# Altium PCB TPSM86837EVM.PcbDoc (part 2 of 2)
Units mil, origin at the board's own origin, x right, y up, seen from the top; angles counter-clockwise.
Board outline 3000 x 2500 mil, 4 copper layers (Top Layer, Signal Layer 1, Signal Layer 2, Bottom Layer), stack 61.2 mil thick; 63 components, 16 nets, 100 pads, 288 vias.
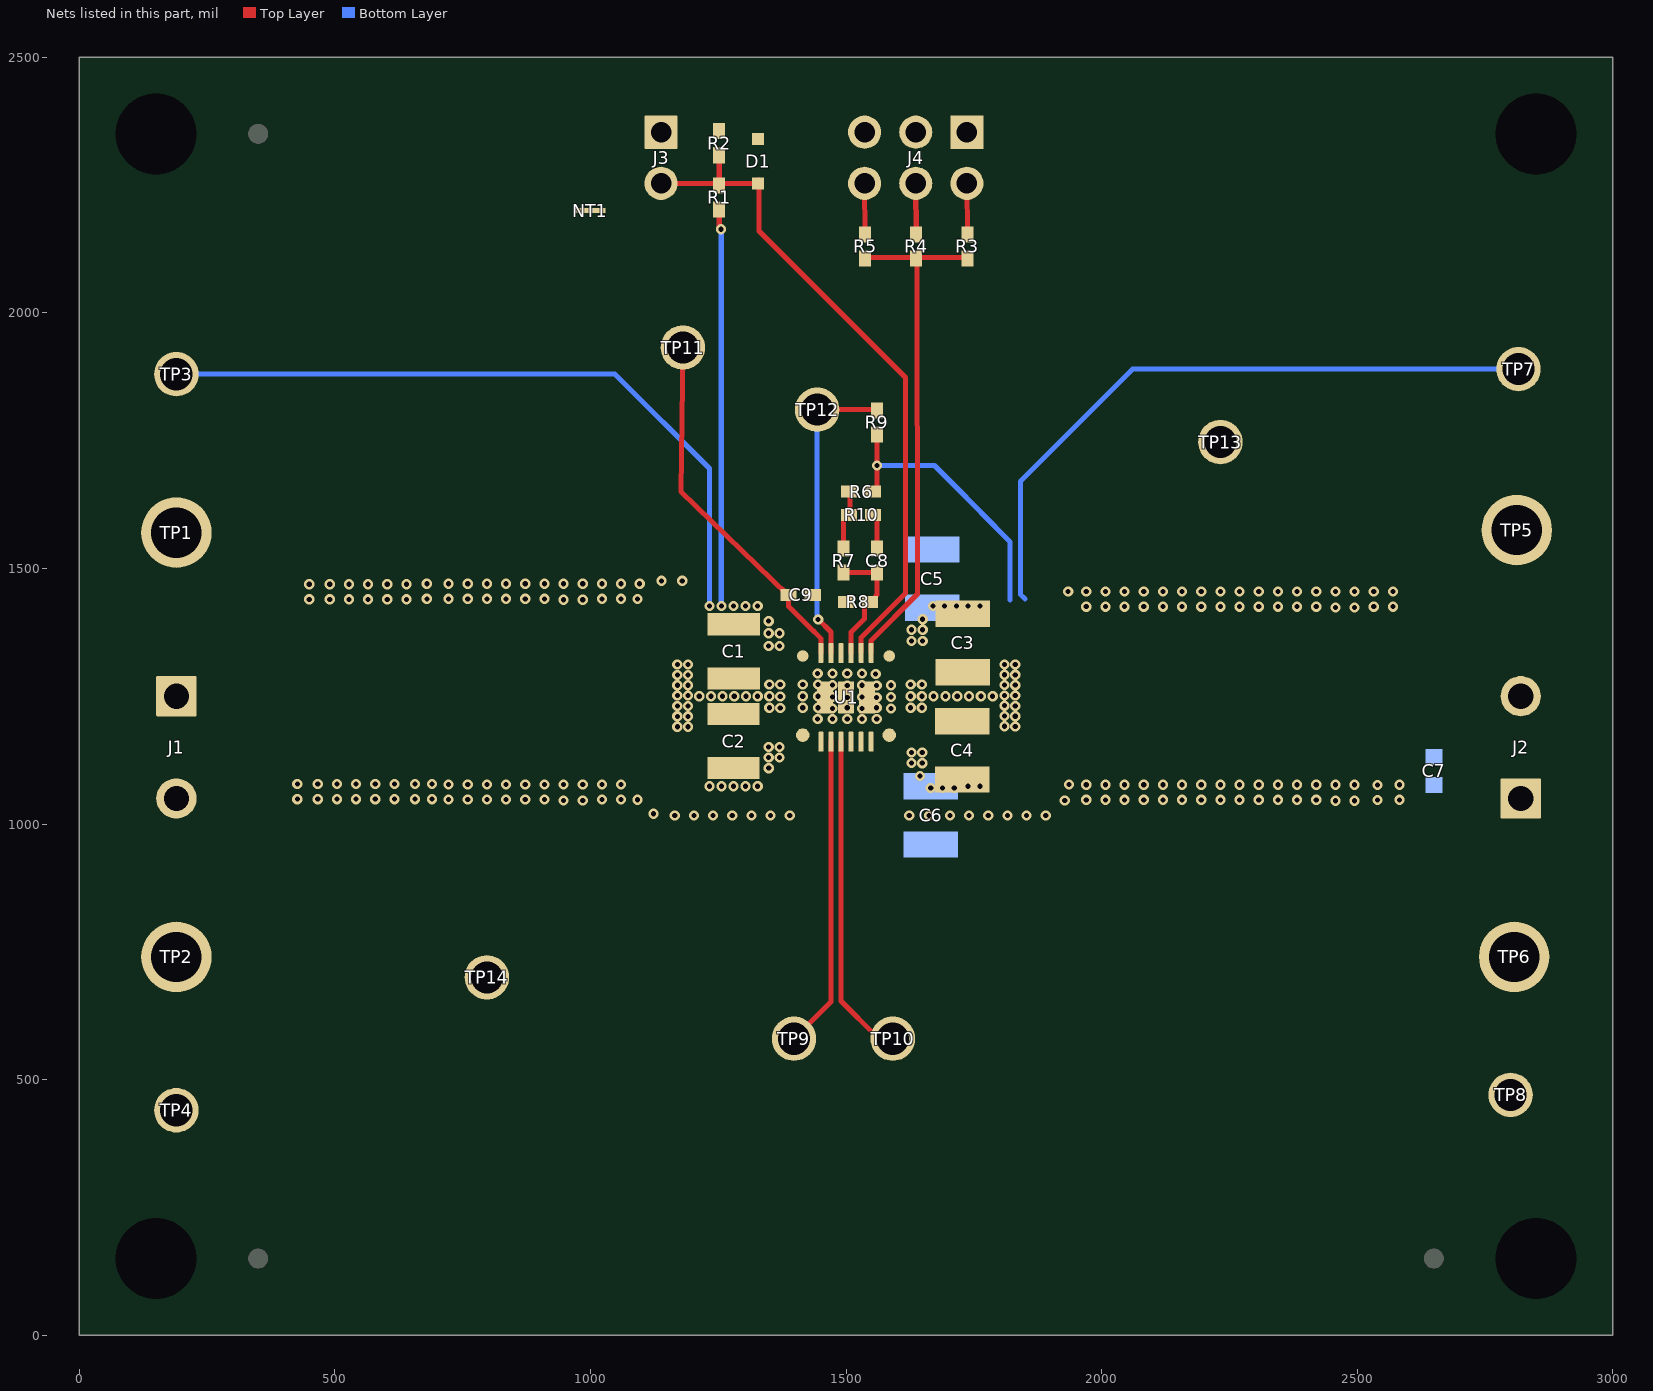
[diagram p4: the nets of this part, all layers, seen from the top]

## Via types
v1: diameter 20, hole 10, Top Layer to Bottom Layer, 288 vias

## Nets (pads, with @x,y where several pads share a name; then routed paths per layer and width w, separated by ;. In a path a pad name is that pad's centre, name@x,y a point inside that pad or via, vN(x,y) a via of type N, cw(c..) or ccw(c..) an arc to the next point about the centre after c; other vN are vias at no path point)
AGND: C9.2 D1.2 J3.1 J4.1 J4.3 J4.5 NT1.1 R2.1 R8.1 U1.5
BOOT: TP10.1 U1.12 | length 640
  Top Layer w10: U1.12@1490.16,1163.39 1490.16,690 1490.16,653.66 1560.12,583.69 TP10.1@1591.5,583.69
EN: D1.1 J3.2 R1.1 R2.2 U1.3 | length 1322
  Top Layer w10: J3.2@1138.16,2253.33 R1.1@1251.94,2253.33 ; R2.2@1251.94,2300.57 R1.1@1251.94,2253.33 ; D1.1@1328.16,2260.02 D1.1@1328.16,2253.33 R1.1@1251.94,2253.33 ; D1.1@1330,2260.02 1330,2253.33 1330,2160 1616.4,1873.6 1616.4,1451.44 1529.53,1364.56 U1.3@1529.53,1336.61
FB: C8.2 R7.1 R8.2 U1.4 | length 251.1
  Top Layer w10: R7.1@1495.19,1491.8 C8.2@1561.02,1491.8 1561.02,1448.33 1557.78,1445.09 1557.78,1441.15 1550.97,1434.34 R8.2@1547.03,1434.34 1543.1,1434.34 1536.28,1427.53 1536.28,1401.47 1509.88,1375.06 U1.4@1509.88,1334.32 ; R8.2@1540.67,1434.34 R8.2@1542.64,1434.34
MODE: R3.2 R4.2 R5.2 U1.2 | length 1007.3
  Top Layer w10: R5.2@1539.29,2108.25 R4.2@1639.06,2108.25 ; U1.2@1549.21,1336.61 1549.21,1358.97 1640.02,1449.78 R4.2@1639.06,2108.25 ; R3.2@1737.34,2108.25 R4.2@1639.06,2108.25
NetC8_1: C8.1 R10.1 | length 68.2
  Top Layer w10: R10.1@1555.12,1604.84 1561.02,1598.94 C8.1@1561.02,1539.04
NetJ4_2: J4.2 R3.1 | length 101.8
  Top Layer w10: J4.2@1736.47,2253.33 R3.1@1737.34,2151.53
NetJ4_4: J4.4 R4.1 | length 103.8
  Top Layer w10: J4.4@1636.47,2253.33 R4.1@1637.34,2149.57
NetJ4_6: J4.6 R5.1 | length 103.8
  Top Layer w10: J4.6@1536.47,2253.33 R5.1@1537.34,2149.57
NetR6_1: R6.1 R7.2 R10.2 | length 115.2
  Top Layer w10: R7.2@1495.19,1539.04 1495.19,1596.09 1503.94,1604.84 1507.87,1604.84 1507.87,1646.29 R6.1@1507.62,1646.55
PG: R9.1 TP12.1 U1.6 | length 627.7
  Top Layer w10: TP12.1@1443.64,1810.59 1559.09,1810.59 R9.1@1560.46,1809.22 R9.1@1560.46,1813.16 ; TP12.1@1444.84,1791.13 TP12.1@1447.07,1788.9 ; v1(1445.55,1400.31) 1470.51,1375.35 U1.6@1470.51,1334.32
  Bottom Layer w10: TP12.1@1439.28,1824.56 1443.64,1820.2 TP12.1@1443.64,1810.59 1443.64,1402.23 v1(1445.55,1400.31)
PGND: C1.1 C2.1 C3.2 C4.2 C5.2 C6.2 C7.2 J1.2 J2.1 NT1.2 TP2.1 TP4.1 TP6.1 TP8.1 TP13.1 TP14.1 U1.13 U1.14 U1.15 U1.17 U1.18 U1.19
  other v1: 1164.89,1016.85 1202.39,1016.85 1239.89,1016.85 1277.39,1016.85 1314.89,1016.85 1352.39,1016.85 1389.89,1016.85 1623.72,1016.85 1662.2,1016.85 1703.18,1016.85 1740.68,1016.85 1778.18,1016.85 1815.68,1016.85 1853.18,1016.85 1890.68,1016.85 1123.67,1020 2457.5,1045.53 2495,1045.53 947.5,1046.21 985,1046.21 1928.04,1046.1 1091.85,1047.45 1970,1047.23 2007.5,1047.23 2045,1047.23 2082.5,1047.23 2120,1047.23 2157.5,1047.23 2195,1047.23 2232.5,1047.23 2270,1047.23 2307.5,1047.23 2345,1047.23 2382.5,1047.23 2420,1047.23 2540,1046.79 2582.95,1047.28 426.65,1048.6 466.65,1048.6 504.15,1048.6 541.65,1048.6 579.15,1048.6 616.65,1048.6 657.07,1048.6 690,1048.6 722.5,1047.92 760,1047.92 797.5,1047.92 835,1047.92 872.5,1047.92 910,1047.92 1022.5,1047.92 1060,1047.92 2540,1076.34 722.5,1077.47 760,1077.47 797.5,1077.47 835,1077.47 872.5,1077.47 910,1077.47 947.5,1077.47 985,1077.47 1022.5,1077.47 1060,1077.47 1936.25,1077.47 1970,1076.79 2007.5,1076.79 2045,1076.79 2082.5,1076.79 2120,1076.79 2157.5,1076.79 2195,1076.79 2232.5,1076.79 2270,1076.79 2307.5,1076.79 2345,1076.79 2382.5,1076.79 2420,1076.79 2457.5,1076.79 2495,1076.79 2582.95,1076.84 426.65,1078.16 466.65,1078.16 504.15,1078.16 541.65,1078.16 579.15,1078.16 616.65,1078.16 657.07,1078.16 690,1078.16 1170,1190.33 1191,1190.33 1810,1191.23 1831,1190.66 1444.59,1205.67 1473.47,1205.67 1502.35,1205.67 1531.24,1205.67 1560.12,1205.67 1170,1210.61 1191,1210.61 1810,1211.36 1831,1210.88 1473.47,1225.87 1531.5,1225.76 1588.27,1225.76 1350,1227.32 1371.29,1226.99 1415.35,1227.32 1445,1227.32 1502.35,1227.32 1560,1227.32 1626.49,1227.32 1648.35,1227.32 1170,1230.89 1191,1230.89 1810,1231.49 1831,1231.11 1473.47,1248.54 1502.35,1247.7 1531.5,1248.44 1560,1247.7 1588.27,1248.44 1212.86,1250 1235.71,1250 1258.57,1250 1281.43,1250 1304.29,1250 1327.14,1250 1350,1250 1371.29,1249.67 1415.35,1250 1445,1250 1626.49,1250 1648.31,1250 1671.41,1250 1694.5,1250 1717.6,1250 1740.7,1250 1763.8,1250 1786.9,1250 1170,1251.16 1191,1251.16 1810,1251.62 1831,1251.33 1170,1271.44 1191,1271.44 1473.47,1271.55 1502.35,1270.71 1531.5,1271.44 1560,1270.71 1588.27,1271.44 1831,1271.55 1810,1271.74 1350,1273.01 1371.29,1272.68 1415.35,1273.01 1445,1273.01 1626.49,1273.01 1648.35,1273.01 1170,1291.72 1191,1291.72 1810,1291.87 1831,1291.78 1444.59,1294.33 1473.47,1294.33 1502.35,1294.33 1531.24,1294.33 1558.07,1293.69 1170,1312 1191,1312 1810,1312 1831,1312 2457.5,1423.41 2495,1423.41 1970,1425.11 2007.5,1425.11 2045,1425.11 2082.5,1425.11 2120,1425.11 2157.5,1425.11 2195,1425.11 2232.5,1425.11 2270,1425.11 2307.5,1425.11 2345,1425.11 2382.5,1425.11 2420,1425.11 2532.5,1425.11 2570,1425.11 450,1439.46 490,1439.46 527.5,1439.46 565,1439.46 602.5,1439.46 640,1439.46 947.5,1438.74 985,1438.74 680,1440.44 722.5,1440.44 760,1440.44 797.5,1440.44 835,1440.44 872.5,1440.44 910,1440.44 1022.5,1440.44 1060,1440.44 1091.85,1439.98 1934.65,1454.67 1970,1454.67 2007.5,1454.67 2045,1454.67 2082.5,1454.67 2120,1454.67 2157.5,1454.67 2195,1454.67 2232.5,1454.67 2270,1454.67 2307.5,1454.67 2345,1454.67 2382.5,1454.67 2420,1454.67 2457.5,1454.67 2495,1454.67 2532.5,1454.67 2570,1454.67 450,1469.02 490,1469.02 527.5,1469.02 565,1469.02 602.5,1469.02 640,1469.02 680,1470 722.5,1470 760,1470 797.5,1470 835,1470 872.5,1470 910,1470 947.5,1470 985,1470 1022.5,1470 1060,1470 1096.38,1470 1139.31,1475.72 1179.74,1475.72
SS: C9.1 TP11.1 U1.7 | length 739.7
  Top Layer w10: TP11.1@1181.01,1932.12 1177.31,1650.13 C9.1@1385.65,1448.33 ; C9.1@1376.8,1455.06 C9.1@1383.69,1448.33 ; C9.1@1376.87,1459.07 1376.87,1455.14 C9.1@1383.69,1448.33 ; U1.7@1450.83,1334.32 1450.83,1363.24 1437.03,1377.04 1436.47,1377.04 1387.62,1425.89 C9.1@1387.62,1448.33 C9.1@1383.69,1448.33
SW: TP9.1 U1.10 U1.11 | length 613.3
  Top Layer w10: TP9.1@1398.27,580 1470.47,652.2 1470.47,690.47 U1.11@1470.47,1163.39
VIN: C1.2 C2.2 J1.1 R1.2 TP1.1 TP3.1 U1.8 U1.9 | length 2165.4
  Top Layer w10: R1.2@1251.94,2202.01 1251.94,2169.75 1255.61,2166.08 v1(1255.61,2163.38)
  Bottom Layer w10: TP3.1@190,1880 1048.15,1880 1232.76,1695.39 v1(1232.76,1426.54) ; v1(1255.61,2163.38) 1256,2162.99 1256,1426.92 v1(1256.38,1426.54)
  other v1: 1232.76,1073.78 1256.38,1073.78 1280,1073.78 1303.62,1073.78 1327.24,1073.78 1348.8,1109.21 1348.76,1130 1370,1130 1348.76,1150.41 1370,1150.41 1348.76,1348.43 1370,1348.43 1348.76,1373.24 1370,1373.24 1348.76,1396.75 1280,1426.54 1303.62,1426.54 1327.24,1426.54
VOUT: C3.1 C4.1 C5.1 C6.1 C7.1 J2.2 R6.2 R9.2 TP5.1 TP7.1 U1.1 U1.16 | length 1851.8
  Top Layer w10: R6.2@1556.97,1646.55 1560.55,1650.13 v1(1560.55,1701.21) 1560.5,1701.25 R9.2@1560.46,1761.97 R9.2@1560.46,1761.97
  Bottom Layer w10: v1(1560.55,1701.21) 1673.22,1701.21 1707.44,1666.99 1820.7,1551.98 1820.7,1438.64 ; 1850,1440.44 1841,1449.45 1841,1670 2061,1890 TP7.1@2815.58,1890
  other v1: 1665.9,1070.63 1688.85,1070.63 1711.8,1070.63 1738.85,1073.78 1761.8,1073.78 1644.96,1093.94 1628.31,1119.29 1649.06,1119.06 1628.31,1140 1649.06,1139.76 1628.31,1357.95 1650,1357.95 1628.31,1379.92 1650,1379.92 1650,1400.63 1670,1426.54 1692.95,1426.54 1715.9,1426.54 1738.85,1426.54 1761.8,1426.54
pads on no net: FID1.1 FID2.1 FID3.1 FID4.1 FID5.1 FID6.1 LBL1.0 MH1.1 MH2.1 MH3.1 MH4.1 SH-JP1.0 SH-JP2.0

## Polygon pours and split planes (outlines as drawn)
VIN on Top Layer "Top Layer-VIN" (solid, remove dead copper, pour order 1012): 1429.26,1190.61 1430.12,1189.75 1430.12,1140.95 1348.76,1059.6 1210,1059.6 1210,1162.36 1373.82,1162.36 1402.36,1190.91
PGND on Top Layer "Top Layer-PGND" (solid, remove dead copper, pour order 1050): 0,2500 3000,2500 3000,0 0,0
AGND on Top Layer "Top Layer-AGND" (solid, remove dead copper, pour order 1032): 1556.1,1317.95 1444.59,1317.95 1444.59,1361.85 1000,1806.43 1000,2520 1798.31,2520 1800,2518.31 1800,1612.05 1556.1,1368.15
VIN on Top Layer "TOP_LAYER_VIN_P1004" (solid, pour order 1004): 1429.43,1309.09 1429.43,1357.72 1348.8,1438.35 1210,1438.35 1210,1337.64 1378.87,1337.64 1402.17,1309.09
VOUT on Top Layer "Top Layer-VOUT" (solid, remove dead copper, pour order 1010): 1599.41,1188.94 1625.98,1162.36 1780,1162.36 1780,1061.56 1648.6,1061.56 1569.88,1140.28 1569.88,1190.91 1597.83,1190.91
VOUT on Top Layer "Top Layer-VOUT 1" (solid, remove dead copper, pour order 1008): 1570.46,1309.67 1569.88,1310.25 1569.88,1355.15 1653.08,1438.35 1781.63,1438.35 1781.64,1337.64 1626.8,1337.64 1598.83,1309.67
VIN on Bottom Layer "Bottom Layer-VIN" (solid, remove dead copper, pour order 1022): 401.51,1392.08 401.51,1621.78 294.96,1740 40.34,1740 40.34,1109.21 1080.21,1109.21 1141.18,1050 1380,1050 1380,1162.36 1150,1162.36 1150,1188.11 1150,1337.64 1380,1337.64 1380,1389.92 1380,1450 1131.46,1450 1082.19,1391.61
PGND on Bottom Layer "Bottom Layer-PGND" (solid, remove dead copper, pour order 1052): -9.89,2506.6 3000.11,2506.6 3000.11,6.6 0.11,6.6 0.11,2496.6
VOUT on Bottom Layer "Bottom Layer-No Net" (solid, remove dead copper, pour order 1030): 3000,1180 3000,1110 1920.24,1110 1889.34,1050 1616.4,1050 1616.4,1165.45 1850,1165.45 1850,1339.77 1616.4,1340 1616.4,1450 1889.34,1450 1920.24,1390 3000,1390 3000,1190
VOUT on Bottom Layer "Bottom Layer-VOUT" (solid, remove dead copper, pour order 1044): 3000,1350 2610.26,1350 2610.26,1633.03 2717.23,1740 3000,1740
PGND on Signal Layer 1 "Signal Layer 1-PGND" (solid, remove dead copper, pour order 1034): -10,2500 3000,2500 3000,0 10,0 -10,20
PGND on Signal Layer 2 "Signal Layer 2-PGND" (solid, remove dead copper, pour order 1036): 0,2500 0,0 3000,0 3000,2500

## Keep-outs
Keep-Out Layer:
  text ".Layer_Name" at 577.16,-874.34 h30

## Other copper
Top Layer:
  rectangle net SW: 1445,1134.4 1475.85,1183.66
  text ".Layer_Name" at 577.16,-874.34 h30
Signal Layer 1:
  text ".Layer_Name" at 577.16,-874.34 h30
Signal Layer 2:
  text ".Layer_Name" at 577.16,-865.84 h30
Bottom Layer:
  text ".Layer_Name" at 577.16,-874.34 h30

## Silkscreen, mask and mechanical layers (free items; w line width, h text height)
Top Overlay:
  text "L" at 1040,2341.91 h30.79
  text "'.PRJ_Number' Rev:'.PCB_Rev'" at 2090,2238.03 h59.69
  text "EN" at 1015,2231.52 h30.71
  text "FSW  / SELECT" at 1786.47,2203.33 h35
  text "1200KHz" at 1416.66,1986.08 h24.41
  text "800KHz" at 1576.31,1986.08 h24.41
  text "500KHz" at 1718.26,1986.08 h24.41
  text "VIN" at 312.29,1539.66 h30
  text "VOUT" at 2590,1537.32 h30
  text "VIN" at 426.65,1271.44 h40
  text "VOUT" at 2457.5,1271.44 h40
  text "PGND" at 2450.13,969.61 h40
  text "PGND" at 426.65,952.56 h40
  text "PGND" at 323.34,700 h30
  text "PGND" at 2590,700 h30
  text ".Layer_Name" at 577.16,-874.34 h30
Bottom Overlay:
  text ".Layer_Name" at 577.16,-874.34 h30
Top Paste:
  text ".Layer_Name" at 577.16,-874.34 h30
Bottom Paste:
  text ".Layer_Name" at 577.16,-874.34 h30
Top Solder:
  text ".Layer_Name" at 577.16,-874.34 h30
  text ".Layer_Name" at 577.16,-874.34 h30
Bottom Solder:
  text ".Layer_Name" at 577.16,-874.34 h30
Drill Guide:
  text ".Layer_Name" at 577.16,-874.34 h30
M1 Board Outline:
  lines w47.24: 0,0 0,2500 ; 0,0 3000,0 ; 0,0 3000,0 ; 0,0 0,2500 ; 0,2500 3000,2500 ; 0,2500 3000,2500 ; 3000,0 3000,2500 ; 3000,0 3000,2500
  text ".Layer_Name" at 577.16,-874.34 h30
M2 Board Dimensions:
  rectangle: 0.16,-290.84 125.16,-165.84
  rectangle: 125.16,-415.84 500.16,-290.84
  lines w7: 0.16,-290.84 1000.16,-290.84 ; 125.16,-415.84 125.16,-165.84 ; 250.16,-415.84 250.16,-165.84 ; 500.16,-415.84 500.16,-165.84 ; 750.16,-415.84 750.16,-165.84 ; 0.16,-415.84 1000.16,-415.84 1000.16,-165.84 0.16,-165.84 0.16,-415.84
  text ".Layer_Name" at 577.16,-874.34 h30
M3 3D STEP Top:
  text ".Layer_Name" at 577.16,-874.34 h30
M4 3D STEP Bottom:
  text ".Layer_Name" at 577.16,-874.34 h30
M5 Assembly Top:
  lines w10: -291.84,-946.01 6308.16,-946.01 ; -291.84,-742.68 6310.16,-742.68 ; -291.84,-539.34 -291.84,-1149.34 3713.16,-1149.34 6310.16,-1149.34 6310.16,-539.34 -291.34,-539.34 -291.34,-1149.34 1284.16,-1149.34 ; 2173.16,-1149.34 2173.16,-539.34 ; 3440.16,-742.68 3440.16,-539.34 ; 4280.16,-742.68 4280.16,-539.34 ; 4902.16,-1155.84 4902.16,-953.01
  text "COMPONENTS MARKED 'DNP' SHOULD NOT BE POPULATED." at 1153.66,-334.34 h30
  text "ASSEMBLY VARIANT:" at 1153.16,-449.84 h30
  text ".VariantName" at 2189.16,-449.84 h30
  text "PCB VIEWED FROM TOP SIDE" at -228.34,-671.51 h30
  text "BOARD #:" at 2248.16,-671.51 h30
  text ".PRJ_Number" at 2793.66,-671.51 h30
  text "REV:" at 3638.16,-671.51 h30
  text ".PCB_Rev" at 3929.66,-671.51 h30
  text "SVN REV:" at 4476.16,-671.51 h30
  text ".VersionControl_RevNumber" at 4982.16,-671.51 h30
  text "TID #:" at 2248.16,-874.84 h30
  text ".TID" at 2793.66,-874.84 h30
  text "PLOT NAME =" at -228.34,-1080.18 h30
  text ".plot_File_Name" at 577.16,-1080.18 h30
  text "GENERATED    :" at 2250.16,-1080.18 h30
  text ".Print_Date" at 3119.66,-1080.18 h30
  text ".Print_Time" at 3848.66,-1080.18 h30
  text "TEXAS INSTRUMENTS" at 5113.16,-1080.18 h30
M6 Assembly Bottom:
  lines w10: -292.34,-743.18 6309.66,-743.18 ; -290.34,-946.51 6309.66,-946.51 ; 1115.66,-1156.34 1115.66,-953.51 ; 1737.66,-743.18 1737.66,-539.84 ; 2577.66,-743.18 2577.66,-539.84 ; 3844.66,-1149.84 3844.66,-539.84 ; 4733.66,-1149.84 6309.16,-1149.84 6309.16,-539.84 -292.34,-539.84 -292.34,-1149.84 2304.66,-1149.84 6309.66,-1149.84 6309.66,-539.84
  text "COMPONENTS MARKED 'DNP' SHOULD NOT BE POPULATED." at 6102.16,-333.84 h30
  text ".VariantName" at 5058.16,-449.84 h30
  text "ASSEMBLY VARIANT:" at 6097.16,-449.84 h30
  text ".VersionControl_RevNumber" at 1035.66,-672.01 h30
  text "SVN REV:" at 1541.66,-672.01 h30
  text ".PCB_Rev" at 2088.16,-672.01 h30
  text "REV:" at 2379.66,-672.01 h30
  text ".PRJ_Number" at 3224.16,-672.01 h30
  text "BOARD #:" at 3769.66,-672.01 h30
  text "PCB VIEWED FROM BOTTOM SIDE" at 6246.16,-672.01 h30
  text ".TID" at 3224.16,-875.34 h30
  text "TID #:" at 3769.66,-875.34 h30
  text "TEXAS INSTRUMENTS" at 904.66,-1080.68 h30
  text ".Print_Time" at 2169.16,-1080.68 h30
  text ".Print_Date" at 2898.16,-1080.68 h30
  text "GENERATED    :" at 3767.66,-1080.68 h30
  text ".plot_File_Name" at 5440.66,-1080.68 h30
  text "PLOT NAME =" at 6246.16,-1080.68 h30
M9 Title Sheet:
  drawing of 57 lines, arcs and shapes, not listed
  text "1" at 739.99,8020.66 h70
  text "2" at 3235.66,8020.66 h70
  text "3" at 5725,8020.66 h70
  text "4" at 8231.67,8020.66 h70
  text "5" at 10730.66,8020.66 h70
  text "6" at 13235.66,8020.66 h70
  text "A" at -416.34,6877.66 h70
  text "A" at 14383.66,6877.66 h70
  text "B" at -416.34,4497.66 h70
  text "B" at 14383.66,4497.66 h70
  text "C" at -416.34,2122.66 h70
  text "C" at 14383.66,2122.66 h70
  text "PROJECT TITLE:" at 11343.66,261.66 h45
  text ".PRJ_Title" at 11393.66,128.33 h70
  text "DESIGNED FOR:" at 11343.66,-39.34 h45
  text ".PRJ_Customer" at 11393.66,-179.34 h70
  text "D" at -416.34,-247.34 h70
  text "D" at 14383.66,-247.34 h70
  text "FILE NAME:" at 11343.66,-339.34 h45
  text ".PCB_File_Name_No_Path" at 11393.66,-459.34 h70
  text "Texas Instruments (TI) and/or its licensors do not warrant the accuracy or completeness of this specification" at 6374.16,-621.18 h45
  text "ENGINEER:" at 11343.66,-629.34 h45
  text "LAYOUT BY:" at 12848.66,-629.34 h45
  text "or any information contained therein. TI and/or its licensors do not warrant that this design will meet" at 6329.17,-733.85 h45
  text ".PRJ_Engineer" at 11393.66,-784.33 h70
  text ".PCB_Layout" at 12899.16,-784.33 h70
  text "the specifications, will be suitable for your application or fit for any particular purpose, or will operate in" at 6329.17,-846.51 h45
  text ".Layer_Name" at 577.16,-874.34 h30
  text "ALTIUM DESIGNER VERSION:" at 12848.66,-939.34 h45
  text "an implementation. TI and/or its licensors do not warrant that the design is production worthy. You should" at 6329.17,-959.18 h45
  text "completely validate and test your design implementation to confirm the system functionality for your application." at 6374.16,-1071.84 h45
  text ".print_Scale" at 11393.66,-1072.67 h70
  text ".Application_BuildNumber" at 12899.16,-1072.67 h70
  text "1" at 739.99,-1279.34 h70
  text "2" at 3235.66,-1279.34 h70
  text "3" at 5725,-1279.34 h70
  text "4" at 8231.67,-1279.34 h70
  text "5" at 10730.66,-1279.34 h70
  text "6" at 13235.66,-1279.34 h70
M10 Fab Notes:
  drawing of 189 lines, arcs and shapes, not listed
  text "DESIGN INFORMATION" at 12382.18,6340.33 h30
  text "MIN. TRACK WIDTH:" at 11737.62,6208.21 h30
  text "8" at 12833.86,6208.21 h30
  text "MIL" at 12988.62,6208.21 h30
  text "MIN. CLEARANCE:" at 11737.62,6084.08 h30
  text "0.2" at 12773.86,6084.08 h30
  text "mm" at 12988.62,6084.08 h30
  text "MIN. VIA PAD SIZE:" at 11737.62,5959.95 h30
  text "19" at 12803.87,5959.96 h30
  text "MIL" at 12988.62,5959.95 h30
  text "0.05mm (2MIL)" at 12432.62,5830.05 h30
  text "MINIMUM ANNULAR RING" at 11408.39,5821.83 h30
  text "EXTERNAL" at 13140.62,5821.83 h30
  text "PER" at 11608.39,5711.71 h30
  text "IPC-D-275 CLASS 2 LEVEL C" at 11828.39,5711.7 h30
  text "MIL, HOLES" at 13316.62,5611.23 h30
  text "+/-" at 12924.16,5602.64 h30
  text "+/-" at 13778.16,5602.64 h30
  text "REGISTRATION TOLERANCES:" at 11408.39,5601.58 h30
  text "METAL" at 12608.16,5601.58 h30
  text "5" at 13184.36,5601.58 h30
  text "3" at 14017.36,5601.58 h30
  text "MIL" at 14133.62,5601.58 h30
  text "HOLE SIZE TOLERANCE (UNLESS OTHERWISE SPECIFIED):" at 11408.39,5503.26 h30
  text "+/-" at 13778.16,5500.39 h30
  text "3" at 14017.36,5499.33 h30
  text "MIL" at 14133.62,5499.32 h30
  text "MATERIAL:" at 11333.62,5361.68 h30
  text "FR-4 High Tg" at 12320.06,5233.15 h30
  text "X" at 12175.62,5225.16 h30
  text "FR-408" at 11754.62,5220.65 h30
  text "OTHER" at 13242.62,5220.65 h30
  text "62 MIL (1.6mm) +/-10%" at 12074.72,5077.62 h30
  text "X" at 11954.62,5075.16 h30
  text "THICKNESS:" at 11408.39,5069.39 h30
  text "OTHER" at 13359.62,5069.39 h30
  text "TOLERANCE:" at 11408.39,4931.08 h30
  text "X" at 12256.62,4931.08 h30
  text "ANSI IPC-6012 TYPE 3 CLASS 2" at 12434.63,4931.08 h30
  text "OTHER +/-" at 12434.62,4786.89 h30
  text "BOW & TWIST:" at 11408.39,4641.7 h30
  text "X" at 12256.62,4641.7 h30
  text "ANSI IPC-6012 TYPE 3 CLASS 2" at 12434.63,4641.7 h30
  text "OTHER +/-" at 12434.62,4495.01 h30
  text "DRILLING:" at 11333.62,4364.39 h30
  text "NC_DRILL FILES" at 13094.62,4259.2 h30
  text "REFERENCE:" at 11408.39,4255.26 h30
  text "X" at 12065.62,4255.16 h30
  text "AS SHOWN" at 12243.62,4255.26 h30
  text "X" at 12966.62,4255.26 h30
  text "OTHER" at 13392.62,4113.01 h30
  text "PTH COPPER THICKNESS:" at 11408.06,4109.48 h30
  text "X" at 12547.3,4109.48 h30
  text "20-30 um" at 12675.29,4109.48 h30
  text "BOARD FINISH:" at 11333.62,3961.88 h30
  text "SILKSCREEN:" at 11488.84,3851.76 h30
  text "X" at 12446.62,3851.76 h30
  text "TOP" at 12563.62,3851.76 h30
  text "X" at 12956.62,3851.76 h30
  text "BOTTOM" at 13074.62,3851.76 h30
  text "SILKSCREEN COLOR:" at 11488.84,3696.57 h30
  text "X" at 12445.62,3696.57 h30
  text "WHITE" at 12563.62,3696.57 h30
  text "OTHER" at 13074.62,3696.57 h30
  text "X" at 12576.62,3553.12 h30
  text "GREEN" at 12694.62,3553.12 h30
  text "OTHER" at 13312.62,3553.12 h30
  text "SOLDER RESIST COLOR:" at 11488.84,3546.25 h30
  text "X" at 12576.62,3398.87 h30
  text "MATTE" at 12694.62,3398.87 h30
  text "SEMI-GLOSS" at 13312.16,3398.23 h30
  text "IMMERSION GOLD (ENIG)" at 12394.62,3226.1 h30
  text "ENEPIG" at 13732.16,3218.87 h30
  text "SURFACE FINISH:" at 11333.62,3217.87 h30
  text "X" at 12216.62,3217.87 h30
  text "IMM. TIN/SILVER OR EQUIV" at 11663.16,3080.56 h30
  text "OTHER" at 13094.62,3076.62 h30
  text "ARRAY/PANEL:" at 11333.62,2921.24 h30
  text "CUT AND TRIM PER M1 BOARD OUTLINE" at 12394.62,2913.02 h30
  text "N.C. ROUTE" at 12394.62,2777.06 h30
  text "X" at 13082.62,2777.06 h30
  text "V. SCORE" at 13260.62,2777.06 h30
  text "CERTIFICATION:" at 11333.62,2647.93 h30
  text "MATERIALS AND WORKMANSHIP FOR ALL PCBS" at 12058.62,2647.93 h30
  text "TO MEET OR EXCEED THE REQUIREMENTS OF:" at 12058.62,2553.87 h30
  text "X" at 11696.13,2425.24 h30
  text "ANSI IPC-A-600F CLASS ->" at 11824.12,2425.24 h30
  text "X" at 13472.13,2425.24 h30
  text "2" at 13582.12,2425.24 h30
  text "1" at 13267.12,2423.74 h30
  text "3" at 13936.12,2423.74 h30
  text "X" at 12508.13,2277.55 h30
  text "RoHS" at 12636.12,2277.55 h30
  text "OTHER" at 13280.52,2277.55 h30
  text "PER ORDER" at 13677.58,2277.55 h30
  text "ALL BOARDS MUST MEET OR EXCEED UL94-V0 REQUIREMENTS." at 11361.16,2123.72 h30
  text "PCB MUST BEAR THE UL94V-0 UL REGISTERED MATERIAL ID NUMBER" at 11361.16,2007.66 h30
  text "ADDITIONAL REQUIREMENTS:" at 11333.62,1838.24 h30
  text "MICROSECTION:" at 11408.39,1731.11 h30
  text "YES" at 12314.12,1731.11 h30
  text "REQUIRED" at 13175.62,1586.78 h30
  text "BARE BOARD ELEC. TEST:" at 11408.39,1583.92 h30
  text "NONE" at 12714.12,1583.92 h30
  text "X" at 13057.62,1583.92 h30
  text "PER ORDER" at 13767.62,1583.92 h30
  text "XX MIL VIAS REQUIRE NON-CONDUCTIVE FILL AND PLANARIZE" at 11576.53,1378.98 h59
  text "XX MIL VIAS REQUIRE CONDUCTIVE FILL AND PLANARIZE" at 11584.53,1275 h30
  text "OUTER XX MIL TRACES REQUIRE 50 OHM SINGLE-ENDED IMPEDANCE" at 11583.55,1111.61 h58
  text "LAYER 2 & 3 (INNER LAYERS) XX MIL WIDE, XX MIL SPACE / TRACES REQUIRE 100 OHM DIFFERENTIAL IMPEDANCE" at 11575.55,875.9 h30
  text ".Layer_Name" at 577.16,-874.34 h30
M11 Gerber Information:
  lines w10: -291.84,-946.01 6308.16,-946.01 ; -291.84,-742.68 6310.16,-742.68 ; -291.84,-539.34 -291.84,-1149.34 3713.16,-1149.34 6310.16,-1149.34 6310.16,-539.34 -291.34,-539.34 -291.34,-1149.34 1284.16,-1149.34 ; 2173.16,-1149.34 2173.16,-539.34 ; 3440.16,-742.68 3440.16,-539.34 ; 4280.16,-742.68 4280.16,-539.34 ; 4902.16,-1155.84 4902.16,-953.01
  text "ALL ARTWORK VIEWED FROM TOP SIDE" at -228.34,-671.51 h30
  text "BOARD #:" at 2248.16,-671.51 h30
  text ".PRJ_Number" at 2793.66,-671.51 h30
  text "REV:" at 3638.16,-671.51 h30
  text ".PCB_Rev" at 3929.66,-671.51 h30
  text "SVN REV:" at 4476.16,-671.51 h30
  text ".VersionControl_RevNumber" at 4982.16,-671.51 h30
  text "LAYER NAME =" at -228.34,-874.34 h30
  text "TID #:" at 2248.16,-874.84 h30
  text ".TID" at 2793.66,-874.84 h30
  text "PLOT NAME =" at -228.34,-1080.18 h30
  text ".plot_File_Name" at 577.16,-1080.18 h30
  text "GENERATED    :" at 2250.16,-1080.18 h30
  text ".Print_Date" at 3119.66,-1080.18 h30
  text ".Print_Time" at 3848.66,-1080.18 h30
  text "TEXAS INSTRUMENTS" at 5113.16,-1080.18 h30
M12 Stackup:
  drawing of 295 lines, arcs and shapes, not listed
  text "Layer" at 9770.34,7769.17 h30
  text "Name" at 9985.3,7769.17 h30
  text "Material" at 10465.17,7769.17 h30
  text "Thickness" at 10905.05,7769.17 h30
  text "Constant" at 11239.97,7769.17 h30
  text "Board Layer Stack" at 11534.9,7769.17 h30
  text "Top Overlay" at 9985.3,7709.17 h30
  text "Top Solder" at 9985.3,7649.17 h30
  text "Solder Resist" at 10465.17,7649.17 h30
  text "0.40mil" at 10905.05,7649.17 h30
  text "3.5" at 11239.97,7649.17 h30
  text "1" at 9770.34,7589.17 h30
  text "Top Layer" at 9985.3,7589.17 h30
  text "2.80mil" at 10905.05,7589.17 h30
  text "Dielectric1" at 9985.3,7529.17 h30
  text "FR-4 High Tg" at 10465.17,7529.17 h30
  text "5.00mil" at 10905.05,7529.17 h30
  text "4.8" at 11239.97,7529.17 h30
  text "2" at 9770.34,7469.17 h30
  text "Signal Layer 1" at 9985.3,7469.17 h30
  text "2.80mil" at 10905.05,7469.17 h30
  text "Dielectric3" at 9985.3,7409.17 h30
  text "FR-4 High Tg" at 10465.17,7409.17 h30
  text "40.00mil" at 10905.05,7409.17 h30
  text "4.8" at 11239.97,7409.17 h30
  text "3" at 9770.34,7349.17 h30
  text "Signal Layer 2" at 9985.3,7349.17 h30
  text "2.80mil" at 10905.05,7349.17 h30
  text "Dielectric2" at 9985.3,7289.17 h30
  text "FR-4 High Tg" at 10465.17,7289.17 h30
  text "5.00mil" at 10905.05,7289.17 h30
  text "4.8" at 11239.97,7289.17 h30
  text "4" at 9770.34,7229.17 h30
  text "Bottom Layer" at 9985.3,7229.17 h30
  text "2.80mil" at 10905.05,7229.17 h30
  text "Bottom Solder" at 9985.3,7169.17 h30
  text "Solder Resist" at 10465.17,7169.17 h30
  text "0.40mil" at 10905.05,7169.17 h30
  text "3.5" at 11239.97,7169.17 h30
  text "Bottom Overlay" at 9985.3,7109.17 h30
  text ".Layer_Name" at 577.16,-874.34 h30
M13 Component Bodies Top:
  text ".Layer_Name" at 577.16,-874.34 h30
M14 Component Bodies Bottom:
  text ".Layer_Name" at 577.16,-874.34 h30
M15 Courtyards Top:
  text ".Layer_Name" at 577.16,-874.34 h30
M16 Courtyards Bottom:
  text ".Layer_Name" at 577.16,-874.34 h30
Drill Drawing:
  circle w10: c7895.24,5831.57 r16.67
  lines w10: 7878.57,5923.24 7911.9,5923.24 7895.24,5889.9 7878.57,5923.24 ; 7878.57,5964.9 7911.9,5964.9 7911.9,5998.24 7878.57,5998.24 7878.57,5964.9 ; 7878.57,6048.24 7886.9,6048.24 7895.24,6039.9 7903.57,6048.24 7911.9,6048.24 7903.57,6056.57 7911.9,6064.9 7903.57,6064.9 7895.24,6073.24 7886.9,6064.9 7878.57,6064.9 7886.9,6056.57 7878.57,6048.24 ; 7878.57,6123.24 7886.9,6123.24 7886.9,6114.9 7903.57,6114.9 7903.57,6123.24 7911.9,6123.24 7911.9,6139.9 7903.57,6139.9 7903.57,6148.24 7886.9,6148.24 7886.9,6139.9 7878.57,6139.9 7878.57,6123.24 ; 7878.57,6189.9 7895.24,6198.24 7911.9,6189.9 7903.57,6206.57 7911.9,6223.24 7895.24,6214.9 7878.57,6223.24 7886.9,6206.57 7878.57,6189.9
  lines w12: 7847.11,5792.4 11153.23,5792.4 ; 7847.11,6242.4 11153.23,6242.4 ; 8138.55,5717.4 8138.55,6317.4 ; 8473.47,5717.4 8473.47,6317.4 ; 9162.27,5717.4 9162.27,6317.4 ; 9431.21,5717.4 9431.21,6317.4 ; 9814.11,5717.4 9814.11,6317.4 ; 10573.88,5717.4 10573.88,6317.4 ; 7847.11,5717.4 11153.23,5717.4 11153.23,6317.4 7847.11,6317.4 7847.11,5717.4
  text "Symbol" at 7892.11,6264.9 h36
  text "Quantity" at 8161.05,6264.9 h36
  text "Finished Hole Size" at 8495.97,6264.9 h36
  text "Plated" at 9184.77,6264.9 h36
  text "Hole Type" at 9453.71,6264.9 h36
  text "Drill Layer Pair" at 9836.61,6264.9 h36
  text "Hole Tolerance" at 10596.38,6264.9 h36
  text "4" at 8161.05,6189.9 h30
  text "159.00mil (4.039mm)" at 8495.97,6189.9 h30
  text "NPTH" at 9184.77,6189.9 h30
  text "Round" at 9453.71,6189.9 h30
  text "Top Layer - Bottom Layer" at 9836.61,6189.9 h30
  text "288" at 8161.05,6114.9 h30
  text "10.00mil (0.254mm)" at 8495.97,6114.9 h30
  text "PTH" at 9184.77,6114.9 h30
  text "Round" at 9453.71,6114.9 h30
  text "Top Layer - Bottom Layer" at 9836.61,6114.9 h30
  text "8" at 8161.05,6039.9 h30
  text "40.00mil (1.016mm)" at 8495.97,6039.9 h30
  text "PTH" at 9184.77,6039.9 h30
  text "Round" at 9453.71,6039.9 h30
  text "Top Layer - Bottom Layer" at 9836.61,6039.9 h30
  text "4" at 8161.05,5964.9 h30
  text "49.21mil (1.250mm)" at 8495.97,5964.9 h30
  text "PTH" at 9184.77,5964.9 h30
  text "Round" at 9453.71,5964.9 h30
  text "Top Layer - Bottom Layer" at 9836.61,5964.9 h30
  text "10" at 8161.05,5889.9 h30
  text "63.00mil (1.600mm)" at 8495.97,5889.9 h30
  text "PTH" at 9184.77,5889.9 h30
  text "Round" at 9453.71,5889.9 h30
  text "Top Layer - Bottom Layer" at 9836.61,5889.9 h30
  text "4" at 8161.05,5814.9 h30
  text "98.43mil (2.500mm)" at 8495.97,5814.9 h30
  text "PTH" at 9184.77,5814.9 h30
  text "Round" at 9453.71,5814.9 h30
  text "Top Layer - Bottom Layer" at 9836.61,5814.9 h30
  text "318 Total" at 8161.05,5739.9 h30
  text ".Layer_Name" at 577.16,-874.34 h30
M17 Embedded Cavity:
  text ".Layer_Name" at 577.16,-874.34 h30
M18 Embedded Assembly:
  text ".Layer_Name" at 577.16,-874.34 h30
M19 Embedded Keepout:
  text ".Layer_Name" at 577.16,-874.34 h30

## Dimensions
0,0 to 0,2500 on M2 Board Dimensions
0,0 to 3000,0 on M2 Board Dimensions
0.16,-415.84 to 1000.16,-415.84 on M2 Board Dimensions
